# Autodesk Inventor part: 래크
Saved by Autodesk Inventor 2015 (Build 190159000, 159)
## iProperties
Created: 2024-11
Part Number: 래크
Material: 일반
Document SubType Name: Modeling
Designer: 102-5
Density: 1 g/cm^3
Appearance: 기본값
Author: 102-5
Author: jhkim
Creation Date: 2024-10-25
Sending System: Autodesk Inventor 2025
Preprocessor: ST-DEVELOPER v20
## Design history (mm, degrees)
node "래크1"
node "솔리드1"
node "기준1"
